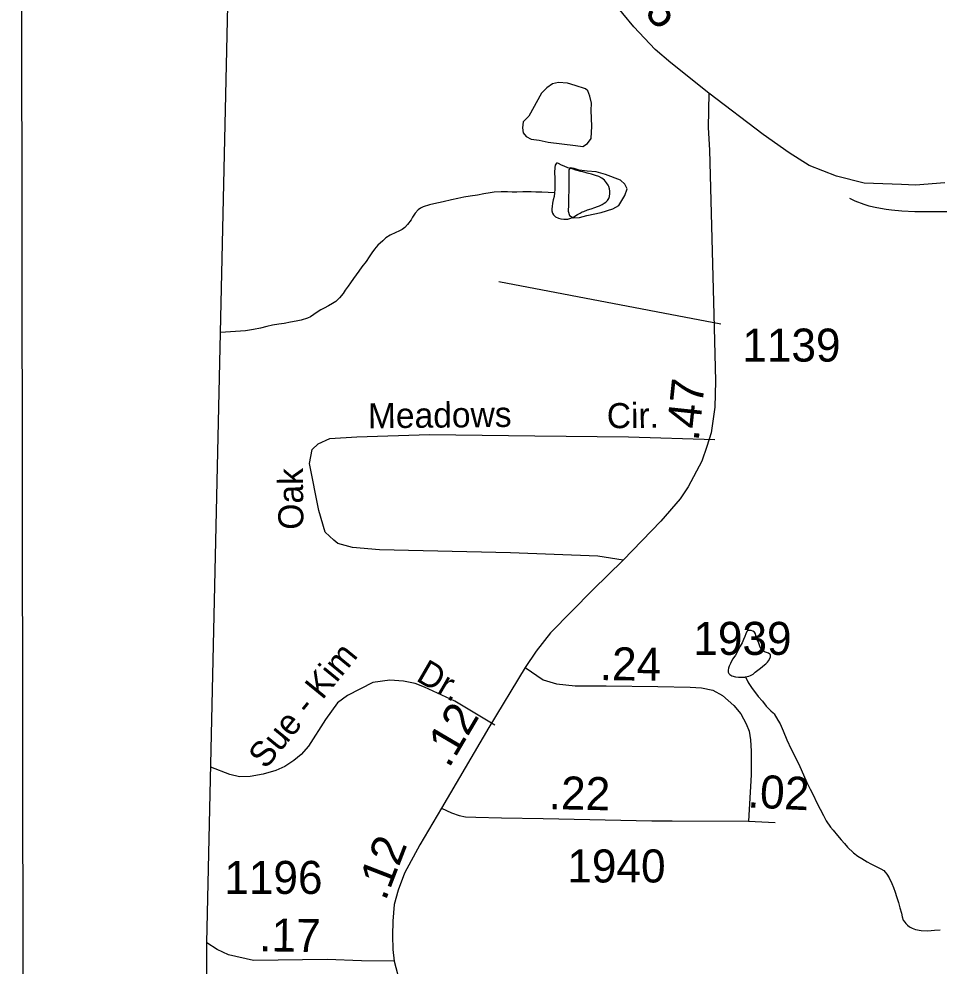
# Model space of a CAD drawing. Extents: x 2126262 to 2293712, y 749403 to 919119.
# Drawn here: x 2133630 to 2137114, y 841115 to 844700 of the extents above; entities that cross this region are included whole.
import ezdxf

# ---------------------------------------------------------------- set-up
doc = ezdxf.new("R2010")
doc.units = 0
for name, color, linetype in [('Exist Boundary Political CountyLine', 7, 'Continuous'), ('Exist Hydrographic Misc Water Feature', 7, 'Continuous'), ('Exist Hydrographic Pond Under 1500 Sq Ft', 7, 'Continuous'), ('Exist Road Non-System Type 51', 7, 'Continuous'), ('Exist Road Non-System Type 51 Label', 7, 'Continuous'), ('Exist Road Primary NC Attributed', 7, 'Continuous'), ('Exist Road Primary NC Service Mileage Hundredths English Label', 7, 'Continuous'), ('Exist Road Secondary Mileage Hundredths English Label', 7, 'Continuous'), ('Exist Road Secondary Type 51 Attributed', 7, 'Continuous'), ('Exist Road Secondary Type 51 Number Label', 7, 'Continuous'), ('Map Preparation Inset Cut Line', 7, 'Continuous')]:
    doc.layers.add(name, color=color, linetype=linetype)

msp = doc.modelspace()

# ---------------------------------------------------------------- linework, layer by layer
at = {"layer": 'Exist Boundary Political CountyLine'}
msp.add_lwpolyline([(2133839.4, 827270.1), (2134339.4, 835334.3), (2134341.8, 841203.1), (2134508, 848637.7), (2140998.3, 864497.6)], dxfattribs=at)
at = {"layer": 'Exist Hydrographic Misc Water Feature'}
msp.add_line((2137022.5, 843971.2), (2137029.6, 843971.2), dxfattribs=at)
for points in [[(2135658, 844042.3), (2135656.2, 844028.3), (2135653.1, 844015.4), (2135650.7, 844002.4), (2135648.6, 843990.1), (2135648, 843981.7), (2135648, 843973.6), (2135650.7, 843964.6), (2135654.8, 843958.7), (2135662.4, 843951.1), (2135672.8, 843946.7), (2135682.4, 843943.2), (2135692.9, 843942.4), (2135709.1, 843942.8), (2135720.2, 843946), (2135730.8, 843951.3), (2135744.6, 843959.4), (2135754.8, 843964.7), (2135762.8, 843969.6), (2135768.8, 843971.9), (2135782.9, 843977.5), (2135796.7, 843981.1), (2135810.6, 843985.9), (2135820.7, 843989.7), (2135828.7, 843992.9), (2135838.5, 843997.5), (2135846.1, 844002.4), (2135852.2, 844006.4), (2135858.4, 844012.7), (2135863.1, 844020.1), (2135866.6, 844028.1), (2135867.4, 844038.9), (2135867.6, 844047.8), (2135866.8, 844057.7), (2135863.9, 844065.8), (2135860.6, 844071.6), (2135855.5, 844080.1), (2135847.5, 844089.8), (2135837.7, 844097.8), (2135825.6, 844103.7), (2135813.5, 844108), (2135797.7, 844112.4), (2135781.1, 844116.9), (2135765.1, 844121.4), (2135757.3, 844122.9), (2135738.6, 844128.2), (2135724.5, 844132.8), (2135709.1, 844137.1), (2135695.2, 844142.5), (2135684.9, 844146.9), (2135673, 844152.8), (2135669.1, 844154.6), (2135665.2, 844154.4), (2135660.9, 844146.5), (2135659.3, 844138.2), (2135657.6, 844118.6), (2135659.7, 844098), (2135659.5, 844084.2), (2135659.9, 844068.3), (2135659.7, 844054.6), (2135658, 844042.3)], [(2135658, 844042.3), (2135609.9, 844044.3), (2135587.9, 844045.1), (2135569.9, 844045.8), (2135554.1, 844045.4), (2135537.9, 844045.4), (2135515.7, 844045.1), (2135497.9, 844044.6), (2135480.1, 844045.2), (2135455.9, 844045.6), (2135430.2, 844044.7), (2135414.2, 844042.3), (2135390, 844037.8), (2135366.1, 844033.7), (2135338.4, 844028.9), (2135314.2, 844025.7), (2135292, 844021), (2135268.7, 844015.2), (2135236.5, 844008.3), (2135218.4, 844004.5), (2135200.6, 843999.9), (2135184.2, 843996.3), (2135160.6, 843989.4), (2135150.7, 843983.9), (2135142.5, 843977.5), (2135130.7, 843965.5), (2135120.8, 843949.9), (2135114.9, 843939.4), (2135101.3, 843921.6), (2135091.1, 843911.4), (2135080.8, 843903.2), (2135069.1, 843896.9), (2135057.7, 843891.3), (2135035.9, 843881.2), (2135019.7, 843871.1), (2135007.8, 843860.3), (2134989.8, 843844.4), (2134976, 843828.2), (2134966.2, 843814.6), (2134956.6, 843799.9), (2134944.7, 843782.2), (2134928.5, 843761.9), (2134917, 843745.9), (2134906.9, 843731.5), (2134896.9, 843717.7), (2134885.4, 843701.6), (2134877.4, 843689.4), (2134865.3, 843673.3), (2134857.7, 843661.1), (2134844, 843644.9), (2134829.8, 843631.2), (2134817.9, 843623.3), (2134802, 843614.7), (2134786, 843605), (2134773.9, 843598.7), (2134760.1, 843589.9), (2134746.4, 843581.4), (2134734.3, 843572.7), (2134722.4, 843568)], [(2136774.6, 844021.4), (2136794.4, 844011.8), (2136828.5, 843999.7)], [(2136828.5, 843999.7), (2136847.4, 843992.9), (2136878.5, 843986.8)], [(2136878.5, 843986.8), (2136913.4, 843979.9), (2136934.3, 843977.7)], [(2136934.3, 843977.7), (2136972.4, 843973.5), (2137022.5, 843971.2)], [(2137029.6, 843971.2), (2137198.2, 843971.8), (2137346.7, 843964.7), (2137398.7, 843958.4)], [(2134722.4, 843568), (2134698.6, 843560.2), (2134680.4, 843555.7), (2134658.6, 843552.1), (2134634.4, 843547.6), (2134614.5, 843545.4), (2134590.3, 843540.9), (2134568.8, 843536.4), (2134544.4, 843530.4), (2134518.8, 843524.5), (2134503.2, 843522.4), (2134488.8, 843520.1), (2134393.4, 843513)], [(2136381.7, 842209.9), (2136394.2, 842212.9), (2136400.1, 842215.2), (2136410, 842220.7), (2136417.8, 842227.2), (2136428, 842235), (2136437.9, 842242.8), (2136445.7, 842249.3), (2136452.6, 842255.2), (2136458.4, 842259.2), (2136464.1, 842265.6), (2136468.4, 842271.1), (2136473.1, 842279.3), (2136475.2, 842285.9), (2136475.2, 842293.2), (2136473.1, 842296.3), (2136468.4, 842299.1), (2136461.2, 842301.8), (2136452.8, 842305.1), (2136447.7, 842307.9), (2136442.6, 842311.9), (2136439.1, 842316.9), (2136434.8, 842326.8), (2136431.1, 842337.6), (2136426.6, 842349.2), (2136423.7, 842357.3), (2136420.6, 842367.1), (2136418.8, 842373.1), (2136415.1, 842378.9), (2136408.5, 842383.2), (2136402.4, 842384.9), (2136396.6, 842385.8), (2136390.1, 842385.1), (2136386.4, 842381.2), (2136382.1, 842373), (2136378.6, 842362.5), (2136373.9, 842351.1), (2136367.9, 842339), (2136360.8, 842326.7), (2136351.1, 842306.3), (2136343.3, 842292.4), (2136333.3, 842278.1), (2136328, 842270), (2136324.1, 842260.9), (2136319.8, 842250.6), (2136317.1, 842242.4), (2136315.9, 842235.7), (2136316.1, 842228.4), (2136317.5, 842222.5), (2136322, 842218.6), (2136329.8, 842214.1), (2136343.1, 842210.5), (2136354.8, 842208.7), (2136365.9, 842208.7), (2136378.2, 842208.8), (2136381.7, 842209.9)], [(2136381.7, 842209.9), (2136390.1, 842190.8), (2136394.2, 842184.9), (2136406.5, 842166.4), (2136414.7, 842155), (2136428.8, 842135.1), (2136445, 842117.6), (2136459, 842099.2), (2136477.2, 842081.4), (2136485.4, 842074.1), (2136489.3, 842069.9), (2136503.7, 842045.8), (2136511.9, 842031.6), (2136523.8, 842005.8), (2136538.1, 841972), (2136554.1, 841936.3), (2136566.4, 841912.6), (2136586.9, 841870.1), (2136601.3, 841838.7), (2136613.6, 841810.5), (2136625.9, 841784.7), (2136635.5, 841766.6), (2136652.1, 841730.8), (2136663.8, 841709.5), (2136676.5, 841685.3), (2136686.8, 841665.5), (2136702.6, 841641.2), (2136712.6, 841629.6), (2136728.8, 841609.6), (2136743.2, 841593.7), (2136755.3, 841579.7), (2136767.6, 841566), (2136789.7, 841544.4), (2136805.9, 841531.8), (2136820.9, 841522.3), (2136842, 841510.5), (2136856, 841502.7), (2136880.2, 841489.4), (2136893.9, 841483.2), (2136904.4, 841477.2), (2136910.3, 841471.4), (2136916, 841463.2), (2136924.4, 841449.8), (2136934.7, 841427.5), (2136941.3, 841412.4), (2136947.6, 841395.1), (2136953.2, 841379.3), (2136960.3, 841356.3), (2136965.5, 841335.7), (2136971.4, 841316.1), (2136973.9, 841301.9), (2136978.2, 841289.5), (2136984.1, 841282.1), (2136987.8, 841276.3), (2136994, 841270.5), (2137002, 841264.4), (2137012, 841258.4), (2137024.1, 841254.2), (2137046, 841250.4), (2137071.5, 841248.2), (2137096.3, 841250.9), (2137118.2, 841252.9)]]:
    msp.add_lwpolyline(points, dxfattribs=at)
at = {"layer": 'Exist Hydrographic Pond Under 1500 Sq Ft'}
for points in [[(2135560.4, 844331.6), (2135539.9, 844310.2), (2135536.7, 844287.5), (2135539.1, 844269.7), (2135550.4, 844255.1), (2135569.8, 844245.4), (2135600.5, 844241.5), (2135634.6, 844234), (2135737.1, 844220.6), (2135765.7, 844217), (2135782.7, 844229.2), (2135796.4, 844247.8), (2135799.7, 844294), (2135797.2, 844353.9), (2135798.1, 844381.4), (2135792.4, 844407.3), (2135784.3, 844427.6), (2135775.7, 844436.1), (2135735.7, 844448.6), (2135707.4, 844456.7), (2135673.4, 844460), (2135650, 844455.1), (2135628.9, 844439.7), (2135608.7, 844419.5), (2135560.4, 844331.6)], [(2135781.4, 844123.6), (2135751, 844128), (2135732.8, 844133.7), (2135716.9, 844136.5), (2135711.8, 844129.2), (2135712.5, 844079.6), (2135710.4, 843997.2), (2135709.5, 843972.8), (2135715.2, 843956.8), (2135728.2, 843947.2), (2135752.7, 843948.3), (2135780.7, 843956), (2135835.1, 843968.2), (2135879.4, 843981.9), (2135901.3, 843994.3), (2135924.9, 844031.9), (2135932.9, 844056.9), (2135924.9, 844075.1), (2135907.8, 844090.5), (2135851.6, 844111.5), (2135816.3, 844121.8), (2135781.4, 844123.6)]]:
    msp.add_lwpolyline(points, dxfattribs=at)
at = {"layer": 'Exist Road Non-System Type 51'}
msp.add_line((2136287.9, 843544.8), (2135446.9, 843704.6), dxfattribs=at)
for points in [[(2135918, 842651.1), (2135821.5, 842667), (2135491.6, 842679.3), (2134995.7, 842690.3), (2134893.6, 842700), (2134837.5, 842714.6), (2134822.8, 842726.8), (2134789.9, 842757.4), (2134765.5, 842839.2), (2134730.2, 843017.4), (2134741.2, 843070.1), (2134763.1, 843092.1), (2134807, 843111.8), (2134910.1, 843118.4), (2135184.4, 843127.2), (2135583.5, 843122.4), (2135938.7, 843118.7), (2136264.7, 843109)], [(2135431.5, 842027.3), (2135281.3, 842117.6), (2135165.3, 842171.3), (2135129.9, 842184.8), (2135085.9, 842193.3), (2135034.7, 842197), (2134970, 842188.4), (2134874.7, 842139.6), (2134836.9, 842111.5), (2134790.5, 842048), (2134726.4, 841947.9), (2134699.5, 841916.1), (2134671.4, 841893), (2134637.3, 841871), (2134603.1, 841855.1), (2134555.5, 841841.7), (2134505.4, 841833.1), (2134465.1, 841831.9), (2134428.5, 841840.5), (2134356.7, 841868.1)]]:
    msp.add_lwpolyline(points, dxfattribs=at)
at = {"layer": 'Exist Road Primary NC Attributed'}
for points in [[(2136241.7, 844419.5), (2136098.5, 844533.7), (2136039.1, 844584.8), (2135958.7, 844670.3), (2135874.8, 844771.8), (2135813.2, 844863.2), (2135772.8, 844931.6), (2135747.7, 845012.6)], [(2137135.4, 844080.1), (2137024.1, 844071.1), (2136972.3, 844073.1), (2136830, 844078.7), (2136725.4, 844105.2), (2136621.5, 844145), (2136546.2, 844193.9), (2136448.2, 844262.5), (2136241.7, 844419.5)]]:
    msp.add_lwpolyline(points, dxfattribs=at)
at = {"layer": 'Exist Road Secondary Type 51 Attributed'}
msp.add_line((2136392.2, 841663.4), (2136493.8, 841658.4), dxfattribs=at)
for points in [[(2136241.7, 844419.5), (2136239.8, 844288.7), (2136244.6, 844203.2), (2136251.9, 843917.3), (2136262.1, 843531.8), (2136266.9, 843329.5), (2136264.7, 843231.2), (2136250.7, 843134.2), (2136235.3, 843082.5), (2136215.6, 843026.4), (2136164.2, 842928.7), (2136133.6, 842883.4), (2136060.8, 842799.2), (2135918, 842651.1), (2135803.2, 842538.8), (2135643.4, 842376.7), (2135588.6, 842307.1), (2135546.8, 842245.2)], [(2135546.8, 842245.2), (2135409.2, 842018), (2135229.6, 841712.4)], [(2135546.8, 842245.2), (2135615.7, 842199.2), (2135665.8, 842184.1), (2135735.9, 842176.6), (2135853.6, 842176.6), (2136049, 842174.1), (2136171.7, 842171.6), (2136214.3, 842169.1), (2136256.9, 842159.1), (2136294.5, 842139.1), (2136337.1, 842101.5), (2136363.6, 842069.8), (2136384.1, 842032.3), (2136394.7, 842003.9), (2136399.7, 841971.4), (2136402.2, 841928.8), (2136402.2, 841838.7), (2136392.2, 841663.4)], [(2135229.6, 841712.4), (2135148.2, 841574.5), (2135090.5, 841467.3), (2135065.6, 841402.2), (2135051.5, 841348.6), (2135045.5, 841284.8), (2135044.2, 841230.5), (2135046.1, 841177.6), (2135050.6, 841134.2)], [(2135229.6, 841712.4), (2135268.7, 841695.9), (2135297.2, 841685), (2135320.6, 841680.6), (2135360.7, 841678.4), (2135457.8, 841676.2), (2135614.5, 841674), (2136026.6, 841665.2), (2136104, 841665.2), (2136392.2, 841663.4)], [(2135050.6, 841134.2), (2134927.2, 841134.8), (2134797.8, 841139.6), (2134518.8, 841136), (2134423.6, 841158), (2134380.9, 841177.5), (2134341.8, 841203.1)], [(2135050.6, 841134.2), (2135075.1, 841042.9), (2135096.2, 840988.7), (2135158.4, 840861.7), (2135287, 840596.8), (2135437.9, 840289.2), (2135544.8, 840069.7)]]:
    msp.add_lwpolyline(points, dxfattribs=at)
at = {"layer": 'Map Preparation Inset Cut Line'}
msp.add_lwpolyline([(2133630.5, 852884.6), (2189691.2, 852884.6), (2189691.2, 811054.9), (2164878.1, 811054.9), (2133665.4, 826054.8)], close=True, dxfattribs=at)

# ---------------------------------------------------------------- texts
at = {"layer": 'Exist Road Non-System Type 51 Label'}
for s, rotation, p in [('Meadows', 0.5857, (2134952.2, 843150.7)), ('Cir.', 0.5857, (2135856.4, 843150.8)), ('Oak', 90.5857, (2134707.8, 842767.5)), ('Sue - Kim', 50.7378, (2134564.7, 841857.6)), ('Dr.', 329.8945, (2135129.8, 842197.8))]:
    msp.add_text(s, height=95, rotation=rotation, dxfattribs=at).set_placement(p)
at = {"layer": 'Exist Road Primary NC Service Mileage Hundredths English Label'}
msp.add_text('.15', height=125, rotation=309.5922, dxfattribs=at).set_placement((2135906.8, 844831.2))
at = {"layer": 'Exist Road Secondary Mileage Hundredths English Label'}
for s, rotation, p in [('.47', 83.9531, (2136203.4, 843099.8)), ('.24', 359.2659, (2135828.7, 842197.8)), ('.12', 59.4908, (2135258.1, 841861.3)), ('.22', 358.7826, (2135635.2, 841709.6)), ('.02', 357.1759, (2136387.1, 841716.3)), ('.12', 68.8138, (2135018, 841359.1)), ('.17', 359.0544, (2134539.5, 841171.6))]:
    msp.add_text(s, height=125, rotation=rotation, dxfattribs=at).set_placement(p)
at = {"layer": 'Exist Road Secondary Type 51 Number Label'}
for s, p in [('1139', (2136369, 843403.2)), ('1939', (2136183.7, 842293.2)), ('1940', (2135706.7, 841431.8)), ('1196', (2134407.9, 841388.4))]:
    msp.add_text(s, height=125, dxfattribs=at).set_placement(p)

doc.saveas('drawing.dxf')
